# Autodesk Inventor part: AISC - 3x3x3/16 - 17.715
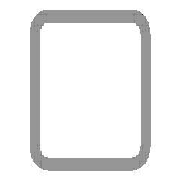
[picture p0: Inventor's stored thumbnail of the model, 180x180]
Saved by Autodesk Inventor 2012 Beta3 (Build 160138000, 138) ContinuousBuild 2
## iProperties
IsCustomPart: 1
Created: 2011-01
Part Number: AISC - 3x3x3/16 - 17.715
Material: Steel, Mild
Description: Tube
Document SubType Name: Modeling
Standard: ANSI
Designer: Beta-8540w
Standards Organization: ANSI
Language: en-US
Size Designation: 3x3x3/16
Categories: <MemberInstance><Categories><Category DisplayName="Structural Shapes" InternalName="089c4875-fa83-4c05-b084-43b9cc11f5ed" Mnemonic="GRDR"><CategoryParameter Dis
Stock Number: 3x3x3/16
Density: 7.86 g/cm^3
_CCFamilyMember: 9
_CCFamilyDisplayName: ANSI AISC (Square) - Tube
_FrameMemberDoc: Frame Member File
_Version: 15.0.0
_GetPNFromCC: 1
G_L: 17.715 in
G_W: 3.000 in
G_H: 3.000 in
Author: Beta-8540w
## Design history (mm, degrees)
node "Start plane"
node "End plane"
sketch "Sketch"
  geometry: L1 (-38.1, -28.575)-(-38.1, 28.575); L2 (-28.575, 38.1)-(28.575, 38.1); L3 (38.1, 28.575)-(38.1, -28.575); L4 (28.575, -38.1)-(-28.575, -38.1); L5 (-28.575, 33.337)-(28.575, 33.338); L6 (33.338, 28.575)-(33.338, -28.575); L7 (28.575, -33.337)-(-28.575, -33.338); L8 (-33.338, -28.575)-(-33.338, 28.575); L9 (0, 56.102)-(0, -56.102) reference; L10 (-56.102, 0)-(56.102, 0) reference; A1 r 9.525 centre (-28.575, -28.575) between (-38.1, -28.575) and (-28.575, -38.1); A2 r 9.525 centre (-28.575, 28.575) between (-28.575, 38.1) and (-38.1, 28.575); A3 r 9.525 centre (28.575, 28.575) between (38.1, 28.575) and (28.575, 38.1); A4 r 9.525 centre (28.575, -28.575) between (28.575, -38.1) and (38.1, -28.575); A5 r 4.763 centre (-28.575, 28.575) between (-28.575, 33.337) and (-33.338, 28.575); A6 r 4.763 centre (28.575, 28.575) between (33.338, 28.575) and (28.575, 33.338); A7 r 4.763 centre (28.575, -28.575) between (28.575, -33.337) and (33.338, -28.575); A8 r 4.763 centre (-28.575, -28.575) between (-33.338, -28.575) and (-28.575, -33.338)
  constraints: 16 end point, 16 point on circle, 8 centre point, 8 tangent, 4 parallel, 3 equal radius, 2 perpendicular, 7 other
  dimensions: "d10" = 76.2 distance between parallel lines of L2 L4 (= G_H); "d11" = 76.2 distance between parallel lines of L1 L3 (= G_W); "d12" = 4.7625 distance between parallel lines of L3 L6 (= G_T); "d15" = 38.1 distance between parallel lines of L2 L10 (= 0.5 x d10); "d16" = 38.1 distance between parallel lines of L9 L3 (= 0.5 x d11); "d17" = 9.525 radius of A1 (= G_IR)
extrude "Body" new body sketch "Sketch" stored distance "d3" = 449.97309 (= G_L); taper "d4" = 0 deg
node "Driven Length"
  sketch "Sketch3"
    geometry: L1 (0, 0)-(10, 0) reference
    constraints: 2 end point, 1 horizontal
  workplane "Work Plane3"
  sketch "Sketch4"
    geometry: L1 (-2, 0)-(12, 0) reference; L2 (-2, 449.973)-(12, 449.973) reference
    dimensions: "d19" = 449.97309 distance between parallel lines of L1 L2 (derived)
body "Solid1"
other parameters: "G_W" = 76.2 [user parameter; used in 1 equation term], "G_H" = 76.2 [user parameter; used in 1 equation term], "G_T" = 4.7625 [user parameter; used in 1 equation term], "G_IR" = 9.525 [user parameter; used in 1 equation term], "G_L" = 449.97309 (= d19) [user parameter; used in 1 equation term], "G_OFFSET_START" = 0 [user parameter; used in 1 equation term], "G_OFFSET_END" = 0 [user parameter; used in 1 equation term], "d13" = 0 (computed from G_OFFSET_START), "d14" = 449.97309 (= G_OFFSET_END + B_L), "B_L" = 449.97309 [user parameter; used in 1 equation term], "d18" = 90 deg
